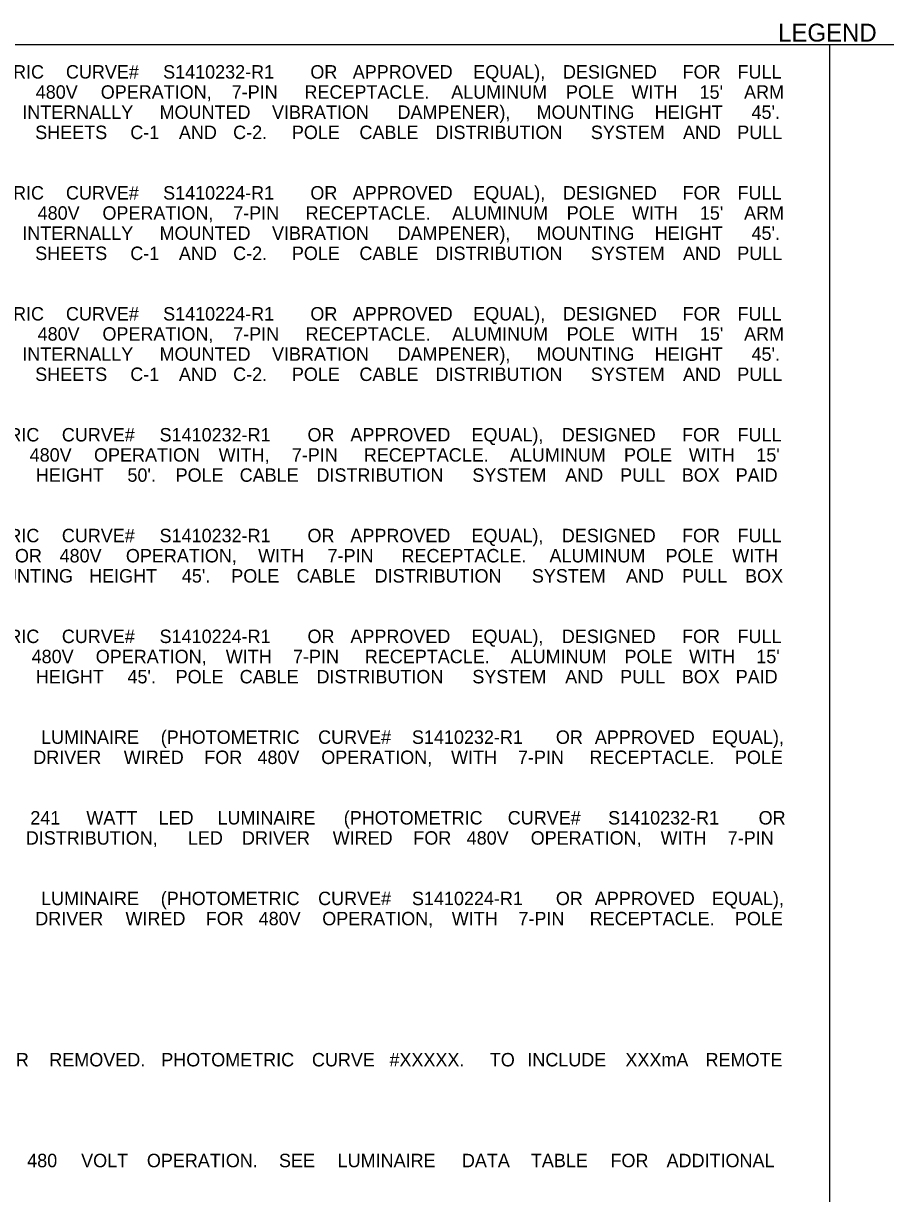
# Model space of a CAD drawing. Extents: x -1452 to -654, y -278 to 245.
# Drawn here: x -1219 to -1026.7, y -16 to 245.2 of the extents above; entities that cross this region are included whole.
import ezdxf

# ---------------------------------------------------------------- set-up
doc = ezdxf.new("R2010")
doc.units = 0
for name, color, linetype in [('Default', 7, 'Continuous'), ('Miscellaneous3', 7, 'Continuous'), ('SheetBorder_dp', 7, 'Continuous')]:
    doc.layers.add(name, color=color, linetype=linetype)

msp = doc.modelspace()

# ---------------------------------------------------------------- linework, layer by layer
at = {"layer": 'Miscellaneous3'}
for p, q in [((-1424.17, 240.54), (-654.17, 240.54)), ((-1039.17, 240.54), (-1039.17, -233.32))]:
    msp.add_line(p, q, dxfattribs=at)

# ---------------------------------------------------------------- texts
at = {"layer": 'Default'}
msp.add_text('LEGEND', height=4, dxfattribs=at).set_placement((-1050.67, 241.19))
at = {"layer": 'SheetBorder_dp'}
for s, p in [('(PHOTOMETRIC ', (-1245.41, 232.93)), ('CURVE# ', (-1209.54, 232.93)), ('S1410232-R1 ', (-1187.86, 232.93)), ('OR ', (-1155.01, 232.93)), ('APPROVED ', (-1145.56, 232.93)), ('EQUAL), ', (-1118.68, 232.93)), ('DESIGNED ', (-1098.66, 232.93)), ('FOR ', (-1071.97, 232.93)), ('FULL ', (-1059.72, 232.93)), ('480V ', (-1216.28, 228.43)), ('OPERATION, ', (-1201.77, 228.43)), ('7-PIN ', (-1172.56, 228.43)), ('RECEPTACLE. ', (-1156.33, 228.43)), ('ALUMINUM ', (-1123.6, 228.43)), ('POLE ', (-1097.99, 228.43)), ('WITH ', (-1083.38, 228.43)), ("15' ", (-1068.18, 228.43)), ('ARM ', (-1058.26, 228.43)), ('INTERNALLY ', (-1219.27, 223.93)), ('MOUNTED ', (-1188.65, 223.93)), ('VIBRATION ', (-1163.57, 223.93)), ('DAMPENER), ', (-1135.57, 223.93)), ('MOUNTING ', (-1104.55, 223.93)), ('HEIGHT ', (-1078.2, 223.93)), ("45'. ", (-1056.6, 223.93)), ('SHEETS ', (-1216.39, 219.43)), ('C-1 ', (-1195.18, 219.43)), ('AND ', (-1184.34, 219.43)), ('C-2. ', (-1172.24, 219.43)), (' POLE ', (-1160.25, 219.43)), ('CABLE ', (-1144.06, 219.43)), ('DISTRIBUTION ', (-1127.08, 219.43)), ('SYSTEM ', (-1092.44, 219.43)), ('AND ', (-1071.88, 219.43)), ('PULL ', (-1059.78, 219.43)), ('(PHOTOMETRIC ', (-1245.41, 205.93)), ('CURVE# ', (-1209.54, 205.93)), ('S1410224-R1 ', (-1187.86, 205.93)), ('OR ', (-1155.01, 205.93)), ('APPROVED ', (-1145.56, 205.93)), ('EQUAL), ', (-1118.68, 205.93)), ('DESIGNED ', (-1098.66, 205.93)), ('FOR ', (-1071.97, 205.93)), ('FULL ', (-1059.72, 205.93)), ('480V ', (-1215.85, 201.43)), ('OPERATION, ', (-1201.39, 201.43)), ('7-PIN ', (-1172.23, 201.43)), ('RECEPTACLE. ', (-1156.06, 201.43)), ('ALUMINUM ', (-1123.39, 201.43)), ('POLE ', (-1097.83, 201.43)), ('WITH ', (-1083.27, 201.43)), ("15' ", (-1068.13, 201.43)), ('ARM ', (-1058.26, 201.43)), ('INTERNALLY ', (-1219.27, 196.93)), ('MOUNTED ', (-1188.65, 196.93)), ('VIBRATION ', (-1163.57, 196.93)), ('DAMPENER), ', (-1135.57, 196.93)), ('MOUNTING ', (-1104.55, 196.93)), ('HEIGHT ', (-1078.2, 196.93)), ("45'. ", (-1056.6, 196.93)), ('SHEETS ', (-1216.39, 192.43)), ('C-1 ', (-1195.18, 192.43)), ('AND ', (-1184.34, 192.43)), ('C-2. ', (-1172.24, 192.43)), (' POLE ', (-1160.25, 192.43)), ('CABLE ', (-1144.06, 192.43)), ('DISTRIBUTION ', (-1127.08, 192.43)), ('SYSTEM ', (-1092.44, 192.43)), ('AND ', (-1071.88, 192.43)), ('PULL ', (-1059.78, 192.43)), ('(PHOTOMETRIC ', (-1245.41, 178.93)), ('CURVE# ', (-1209.54, 178.93)), ('S1410224-R1 ', (-1187.86, 178.93)), ('OR ', (-1155.01, 178.93)), ('APPROVED ', (-1145.56, 178.93)), ('EQUAL), ', (-1118.68, 178.93)), ('DESIGNED ', (-1098.66, 178.93)), ('FOR ', (-1071.97, 178.93)), ('FULL ', (-1059.72, 178.93)), ('480V ', (-1215.85, 174.43)), ('OPERATION, ', (-1201.39, 174.43)), ('7-PIN ', (-1172.23, 174.43)), ('RECEPTACLE. ', (-1156.06, 174.43)), ('ALUMINUM ', (-1123.39, 174.43)), ('POLE ', (-1097.83, 174.43)), ('WITH ', (-1083.27, 174.43)), ("15' ", (-1068.13, 174.43)), ('ARM ', (-1058.26, 174.43)), ('INTERNALLY ', (-1219.27, 169.93)), ('MOUNTED ', (-1188.65, 169.93)), ('VIBRATION ', (-1163.57, 169.93)), ('DAMPENER), ', (-1135.57, 169.93)), ('MOUNTING ', (-1104.55, 169.93)), ('HEIGHT ', (-1078.2, 169.93)), ("45'. ", (-1056.6, 169.93)), ('SHEETS ', (-1216.39, 165.43)), ('C-1 ', (-1195.18, 165.43)), ('AND ', (-1184.34, 165.43)), ('C-2. ', (-1172.24, 165.43)), (' POLE ', (-1160.25, 165.43)), ('CABLE ', (-1144.06, 165.43)), ('DISTRIBUTION ', (-1127.08, 165.43)), ('SYSTEM ', (-1092.44, 165.43)), ('AND ', (-1071.88, 165.43)), ('PULL ', (-1059.78, 165.43)), ('(PHOTOMETRIC ', (-1246.45, 151.93)), ('CURVE# ', (-1210.45, 151.93)), ('S1410232-R1 ', (-1188.64, 151.93)), ('OR ', (-1155.65, 151.93)), ('APPROVED ', (-1146.08, 151.93)), ('EQUAL), ', (-1119.07, 151.93)), ('DESIGNED ', (-1098.92, 151.93)), ('FOR ', (-1072.1, 151.93)), ('FULL ', (-1059.72, 151.93)), ('480V ', (-1217.63, 147.43)), ('OPERATION ', (-1203.27, 147.43)), ('WITH, ', (-1175.48, 147.43)), ('7-PIN ', (-1159.15, 147.43)), ('RECEPTACLE. ', (-1143.08, 147.43)), ('ALUMINUM ', (-1110.5, 147.43)), ('POLE ', (-1085.04, 147.43)), ('WITH ', (-1070.58, 147.43)), ("15' ", (-1055.53, 147.43)), ('HEIGHT ', (-1216.23, 142.93)), ("50'. ", (-1195.82, 142.93)), ('POLE ', (-1185.07, 142.93)), ('CABLE ', (-1170.78, 142.93)), ('DISTRIBUTION ', (-1153.65, 142.93)), ('SYSTEM ', (-1118.87, 142.93)), ('AND ', (-1098.16, 142.93)), ('PULL ', (-1085.91, 142.93)), ('BOX ', (-1072.14, 142.93)), ('PAID ', (-1060.13, 142.93)), ('(PHOTOMETRIC ', (-1246.45, 129.43)), ('CURVE# ', (-1210.45, 129.43)), ('S1410232-R1 ', (-1188.64, 129.43)), ('OR ', (-1155.65, 129.43)), ('APPROVED ', (-1146.08, 129.43)), ('EQUAL), ', (-1119.07, 129.43)), ('DESIGNED ', (-1098.92, 129.43)), ('FOR ', (-1072.1, 129.43)), ('FULL ', (-1059.72, 129.43)), ('FOR ', (-1223.36, 124.93)), ('480V ', (-1210.95, 124.93)), ('OPERATION, ', (-1196.16, 124.93)), ('WITH ', (-1166.66, 124.93)), ('7-PIN ', (-1151.18, 124.93)), ('RECEPTACLE. ', (-1134.68, 124.93)), ('ALUMINUM ', (-1101.67, 124.93)), ('POLE ', (-1075.78, 124.93)), ('WITH ', (-1060.89, 124.93)), ('MOUNTING ', (-1229.81, 120.43)), ('HEIGHT ', (-1204.37, 120.43)), ("45'. ", (-1183.68, 120.43)), ('POLE ', (-1172.65, 120.43)), ('CABLE ', (-1158.08, 120.43)), ('DISTRIBUTION ', (-1140.67, 120.43)), ('SYSTEM ', (-1105.6, 120.43)), ('AND ', (-1084.61, 120.43)), ('PULL ', (-1072.08, 120.43)), ('BOX ', (-1058.03, 120.43)), ('(PHOTOMETRIC ', (-1246.45, 106.93)), ('CURVE# ', (-1210.45, 106.93)), ('S1410224-R1 ', (-1188.64, 106.93)), ('OR ', (-1155.65, 106.93)), ('APPROVED ', (-1146.08, 106.93)), ('EQUAL), ', (-1119.07, 106.93)), ('DESIGNED ', (-1098.92, 106.93)), ('FOR ', (-1072.1, 106.93)), ('FULL ', (-1059.72, 106.93)), ('480V ', (-1217.19, 102.43)), ('OPERATION, ', (-1202.89, 102.43)), ('WITH ', (-1173.88, 102.43)), ('7-PIN ', (-1158.88, 102.43)), ('RECEPTACLE. ', (-1142.86, 102.43)), ('ALUMINUM ', (-1110.34, 102.43)), ('POLE ', (-1084.93, 102.43)), ('WITH ', (-1070.52, 102.43)), ("15' ", (-1055.53, 102.43)), ('HEIGHT ', (-1216.23, 97.93)), ("45'. ", (-1195.82, 97.93)), ('POLE ', (-1185.07, 97.93)), ('CABLE ', (-1170.78, 97.93)), ('DISTRIBUTION ', (-1153.65, 97.93)), ('SYSTEM ', (-1118.87, 97.93)), ('AND ', (-1098.16, 97.93)), ('PULL ', (-1085.91, 97.93)), ('BOX ', (-1072.14, 97.93)), ('PAID ', (-1060.13, 97.93)), ('LUMINAIRE ', (-1215.09, 84.43)), ('(PHOTOMETRIC ', (-1188.39, 84.43)), ('CURVE# ', (-1153.28, 84.43)), ('S1410232-R1 ', (-1132.35, 84.43)), ('OR ', (-1100.24, 84.43)), ('APPROVED ', (-1091.55, 84.43)), ('EQUAL), ', (-1065.42, 84.43)), ('DRIVER ', (-1216.82, 79.93)), ('WIRED ', (-1196.63, 79.93)), ('FOR ', (-1178.67, 79.93)), ('480V ', (-1166.82, 79.93)), ('OPERATION, ', (-1152.58, 79.93)), ('WITH ', (-1123.63, 79.93)), ('7-PIN ', (-1108.71, 79.93)), ('RECEPTACLE. ', (-1092.76, 79.93)), ('POLE ', (-1060.3, 79.93)), ('241 ', (-1217.48, 66.43)), ('WATT ', (-1204.98, 66.43)), ('LED ', (-1188.87, 66.43)), ('LUMINAIRE ', (-1175.73, 66.43)), ('(PHOTOMETRIC ', (-1147.57, 66.43)), ('CURVE# ', (-1110.98, 66.43)), ('S1410232-R1 ', (-1088.59, 66.43)), ('OR ', (-1055.02, 66.43)), ('DISTRIBUTION, ', (-1218.49, 61.93)), ('LED ', (-1182.33, 61.93)), ('DRIVER ', (-1170.26, 61.93)), ('WIRED ', (-1150.03, 61.93)), ('FOR ', (-1132.04, 61.93)), ('480V ', (-1120.14, 61.93)), ('OPERATION, ', (-1105.86, 61.93)), ('WITH ', (-1076.88, 61.93)), ('7-PIN ', (-1061.91, 61.93)), ('LUMINAIRE ', (-1215.09, 48.43)), ('(PHOTOMETRIC ', (-1188.39, 48.43)), ('CURVE# ', (-1153.28, 48.43)), ('S1410224-R1 ', (-1132.35, 48.43)), ('OR ', (-1100.24, 48.43)), ('APPROVED ', (-1091.55, 48.43)), ('EQUAL), ', (-1065.42, 48.43)), ('DRIVER ', (-1216.38, 43.93)), ('WIRED ', (-1196.25, 43.93)), ('FOR ', (-1178.35, 43.93)), ('480V ', (-1166.54, 43.93)), ('OPERATION, ', (-1152.36, 43.93)), ('WITH ', (-1123.47, 43.93)), ('7-PIN ', (-1108.6, 43.93)), ('RECEPTACLE. ', (-1092.7, 43.93)), ('POLE ', (-1060.3, 43.93)), ('DRIVER ', (-1232.96, 12.43)), ('REMOVED. ', (-1213.24, 12.43)), ('PHOTOMETRIC ', (-1188.27, 12.43)), ('CURVE ', (-1154.66, 12.43)), ('#XXXXX. ', (-1137.37, 12.43)), ('TO ', (-1114.98, 12.43)), ('INCLUDE ', (-1106.61, 12.43)), ('XXXmA ', (-1084.73, 12.43)), ('REMOTE ', (-1066.85, 12.43)), ('480 ', (-1218.18, -10.07)), ('VOLT ', (-1206.14, -10.07)), ('OPERATION. ', (-1191.48, -10.07)), ('SEE ', (-1162.01, -10.07)), ('LUMINAIRE ', (-1148.92, -10.07)), ('DATA ', (-1121.21, -10.07)), ('TABLE ', (-1105.82, -10.07)), ('FOR ', (-1088.06, -10.07)), ('ADDITIONAL ', (-1075.55, -10.07))]:
    msp.add_text(s, height=3, dxfattribs=at).set_placement(p)

doc.saveas('drawing.dxf')
